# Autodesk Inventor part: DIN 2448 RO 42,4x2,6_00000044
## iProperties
Created: 2006-03
Part Number: DIN 2448 RO 42,4x2,6_00000044
Material: Default
Document SubType Name: Modeling
Designer: Carlo
Stock Number: DIN 2448 RO 42,4x2,6
Mass: 666.432 g
Surface Area: 5139.94 cm^2
Volume: 666.432 cm^3
Density: 1 g/cm^3
G_L: 2080.000 mm
G_W: 42.400 mm
G_H: 42.400 mm
AFG_Item: 42.4 x 2.6
CSToolsMass: 1.0
CSToolsVolume: 666432.0
CSToolsArea: 5140.0
Author: Carlo
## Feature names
1. AFG_Detailed_DIN 2448 RO 42,4x2,6_00000044 [Extrusion]
2. AFG_Simplified_DIN 2448 RO 42,4x2,6_00000044 [Extrusion]
3. AFG_EndExtrusion_1 [Extrusion]
4. AFG_EndExtrusion_2 [Extrusion]
5. AFG_StartExtrusion_1 [Extrusion]
6. AFG_StartExtrusion_2 [Extrusion]
